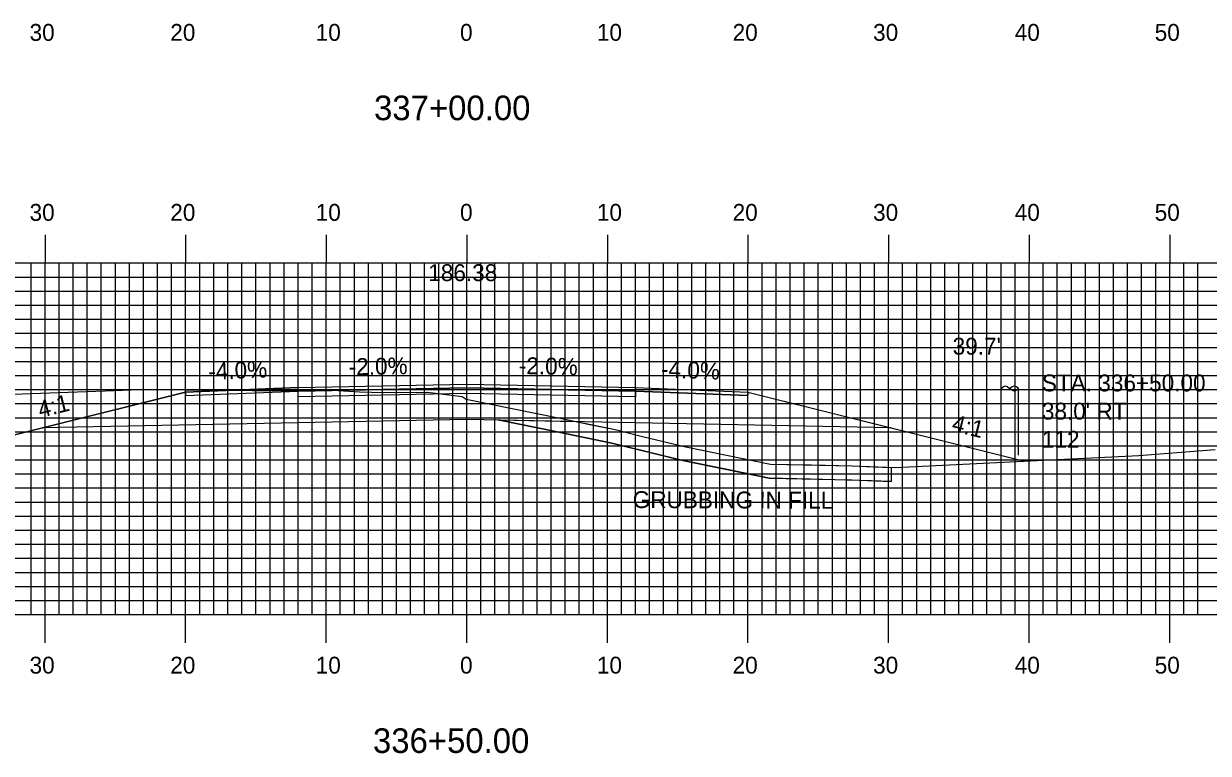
# Model space of a CAD drawing. Extents: x 1823571 to 1823914, y 442310 to 442530.
# Drawn here: x 1823705.4 to 1823789.6, y 442363.2 to 442415.1 of the extents above; entities that cross this region are included whole.
import ezdxf

# ---------------------------------------------------------------- set-up
doc = ezdxf.new("R2010")
doc.units = 0
for name, color, linetype in [('ANNOTATION', 7, 'Continuous'), ('D_Drainage_Text', 7, 'Continuous'), ('D_Roadway_Centerline', 7, 'Continuous'), ('D_Roadway_Centerline_Text', 7, 'Continuous'), ('D_Roadway_Edge_Shoulder', 7, 'Continuous'), ('D_Roadway_Edge_TW', 7, 'Continuous'), ('D_Roadway_Pavement', 7, 'Continuous'), ('D_Roadway_SlopeLines', 7, 'Continuous'), ('D_Roadway_SubGrade', 7, 'Continuous'), ('D_Text_Standard', 7, 'Continuous'), ('D_Utilities_Pole_Joint', 7, 'Continuous'), ('GRUBBING IN FILL', 7, 'Continuous'), ('H_V ANNOTATION', 7, 'Continuous'), ('MAJOR', 7, 'Continuous'), ('MINOR', 7, 'Continuous'), ('S_Roadway_Centerline', 7, 'Continuous')]:
    doc.layers.add(name, color=color, linetype=linetype)

msp = doc.modelspace()

# ---------------------------------------------------------------- linework, layer by layer
at = {"layer": 'D_Roadway_Centerline'}
msp.add_lwpolyline([(1823679.402, 442384.927), (1823702.726, 442385.394), (1823706.726, 442386.394), (1823716.9, 442388.937), (1823724.9, 442389.257), (1823736.9, 442389.497), (1823748.9, 442389.257), (1823756.9, 442388.937), (1823767.074, 442386.394), (1823771.074, 442385.394), (1823776.57, 442384.02)], dxfattribs=at)
at = {"layer": 'D_Roadway_Edge_Shoulder'}
for points in [[(1823724.9, 442389.257), (1823716.9, 442388.937), (1823716.9, 442388.687), (1823724.9, 442389.007)], [(1823748.9, 442389.257), (1823756.9, 442388.937), (1823756.9, 442388.687), (1823748.9, 442389.007)]]:
    msp.add_lwpolyline(points, close=True, dxfattribs=at)
at = {"layer": 'D_Roadway_Edge_TW'}
msp.add_lwpolyline([(1823724.9, 442389.007), (1823724.9, 442389.257), (1823736.9, 442389.497), (1823748.9, 442389.257), (1823748.9, 442389.007), (1823736.9, 442389.247)], close=True, dxfattribs=at)
at = {"layer": 'D_Roadway_Pavement'}
msp.add_lwpolyline([(1823724.9, 442388.59), (1823724.9, 442389.007), (1823736.9, 442389.247), (1823748.9, 442389.007), (1823748.9, 442388.59), (1823736.9, 442388.83)], close=True, dxfattribs=at)
at = {"layer": 'D_Roadway_SlopeLines'}
for points in [[(1823716.9, 442388.937), (1823702.726, 442385.394), (1823679.402, 442384.927)], [(1823756.9, 442388.937), (1823771.074, 442385.394), (1823776.57, 442384.02)]]:
    msp.add_lwpolyline(points, dxfattribs=at)
at = {"layer": 'D_Roadway_SubGrade'}
msp.add_lwpolyline([(1823724.9, 442386.757), (1823706.726, 442386.394), (1823716.9, 442388.937), (1823716.9, 442388.687), (1823724.9, 442389.007), (1823736.9, 442389.247), (1823748.9, 442389.007), (1823756.9, 442388.687), (1823756.9, 442388.937), (1823767.074, 442386.394), (1823748.9, 442386.757), (1823736.9, 442386.997)], close=True, dxfattribs=at)
at = {"layer": 'D_Utilities_Pole_Joint'}
for p, q in [((1823774.9, 442389.195), (1823775.056, 442389.305)), ((1823774.9, 442384.437), (1823774.9, 442389.195)), ((1823775.369, 442389.305), (1823775.525, 442389.195)), ((1823775.681, 442389.305), (1823775.525, 442389.195)), ((1823775.525, 442389.195), (1823775.681, 442389.084)), ((1823776.15, 442389.195), (1823775.994, 442389.305)), ((1823775.994, 442389.084), (1823776.15, 442389.195)), ((1823776.15, 442384.437), (1823776.15, 442389.195))]:
    msp.add_line(p, q, dxfattribs=at)
for centre, start, end in [((1823775.213, 442389.084), 90, 125.26439), ((1823775.213, 442389.084), 54.73561, 90), ((1823775.838, 442389.084), 90, 125.26439), ((1823775.838, 442389.305), 234.73561, 270), ((1823775.838, 442389.084), 54.73561, 90), ((1823775.838, 442389.305), 270, 305.26439)]:
    msp.add_arc(centre, 0.271, start, end, dxfattribs=at)
at = {"layer": 'GRUBBING IN FILL'}
msp.add_line((1823767.074, 442383.583), (1823767.074, 442382.582), dxfattribs=at)
msp.add_line((1823767.074, 442383.583), (1823767.074, 442382.582), dxfattribs=at)
msp.add_lwpolyline([(1823739.136, 442386.952), (1823743.435, 442386.073), (1823747.225, 442385.296), (1823749.15, 442384.817), (1823752.254, 442384.07), (1823758.395, 442382.822), (1823764.285, 442382.683), (1823767.074, 442382.582)], dxfattribs=at)
msp.add_lwpolyline([(1823739.136, 442386.952), (1823743.435, 442386.073), (1823747.225, 442385.296), (1823749.15, 442384.817), (1823752.254, 442384.07), (1823758.395, 442382.822), (1823764.285, 442382.683), (1823767.074, 442382.582)], dxfattribs=at)
msp.add_lwpolyline([(1823739.136, 442386.952), (1823744.664, 442386.842), (1823745.541, 442386.662), (1823747.447, 442386.271), (1823749.388, 442385.788), (1823752.471, 442385.046), (1823755.489, 442384.433), (1823758.507, 442383.819), (1823761.411, 442383.751), (1823764.315, 442383.682), (1823765.837, 442383.627), (1823767.074, 442383.583), (1823767.074, 442382.582), (1823765.68, 442382.632), (1823761.34, 442382.752), (1823758.395, 442382.822), (1823755.324, 442383.446), (1823752.254, 442384.07), (1823750.702, 442384.443), (1823747.225, 442385.296), (1823743.435, 442386.073)], close=True, dxfattribs=at)
msp.add_lwpolyline([(1823739.136, 442386.952), (1823744.664, 442386.842), (1823745.541, 442386.662), (1823747.447, 442386.271), (1823749.388, 442385.788), (1823752.471, 442385.046), (1823755.489, 442384.433), (1823758.507, 442383.819), (1823761.411, 442383.751), (1823764.315, 442383.682), (1823765.837, 442383.627), (1823767.074, 442383.583), (1823767.074, 442382.582), (1823765.68, 442382.632), (1823761.34, 442382.752), (1823758.395, 442382.822), (1823755.324, 442383.446), (1823752.254, 442384.07), (1823750.702, 442384.443), (1823747.225, 442385.296), (1823743.435, 442386.073)], close=True, dxfattribs=at)
at = {"layer": 'MAJOR'}
for p, q in [((1823706.9, 442400.119), (1823706.9, 442398.115)), ((1823716.9, 442400.119), (1823716.9, 442398.115)), ((1823726.9, 442400.119), (1823726.9, 442398.115)), ((1823736.9, 442400.119), (1823736.9, 442398.115)), ((1823746.9, 442400.119), (1823746.9, 442398.115)), ((1823756.9, 442400.119), (1823756.9, 442398.115)), ((1823766.9, 442400.119), (1823766.9, 442398.115)), ((1823776.9, 442400.119), (1823776.9, 442398.115)), ((1823786.9, 442400.119), (1823786.9, 442398.115)), ((1823596.9, 442398.115), (1823876.9, 442398.115)), ((1823596.9, 442398.115), (1823876.9, 442398.115)), ((1823706.9, 442373.115), (1823706.9, 442398.115)), ((1823716.9, 442373.115), (1823716.9, 442398.115)), ((1823726.9, 442373.115), (1823726.9, 442398.115)), ((1823736.9, 442373.115), (1823736.9, 442398.115)), ((1823746.9, 442373.115), (1823746.9, 442398.115)), ((1823756.9, 442373.115), (1823756.9, 442398.115)), ((1823766.9, 442373.115), (1823766.9, 442398.115)), ((1823776.9, 442373.115), (1823776.9, 442398.115)), ((1823786.9, 442373.115), (1823786.9, 442398.115)), ((1823596.9, 442393.115), (1823876.9, 442393.115)), ((1823596.9, 442388.115), (1823876.9, 442388.115)), ((1823596.9, 442383.115), (1823876.9, 442383.115)), ((1823596.9, 442378.115), (1823876.9, 442378.115)), ((1823596.9, 442373.115), (1823876.9, 442373.115)), ((1823706.9, 442371.111), (1823706.9, 442373.115)), ((1823716.9, 442371.111), (1823716.9, 442373.115)), ((1823726.9, 442371.111), (1823726.9, 442373.115)), ((1823736.9, 442371.111), (1823736.9, 442373.115)), ((1823746.9, 442371.111), (1823746.9, 442373.115)), ((1823756.9, 442371.111), (1823756.9, 442373.115)), ((1823766.9, 442371.111), (1823766.9, 442373.115)), ((1823776.9, 442371.111), (1823776.9, 442373.115)), ((1823786.9, 442371.111), (1823786.9, 442373.115))]:
    msp.add_line(p, q, dxfattribs=at)
at = {"layer": 'MINOR'}
for p, q in [((1823705.9, 442373.115), (1823705.9, 442398.115)), ((1823707.9, 442373.115), (1823707.9, 442398.115)), ((1823708.9, 442373.115), (1823708.9, 442398.115)), ((1823709.9, 442373.115), (1823709.9, 442398.115)), ((1823710.9, 442373.115), (1823710.9, 442398.115)), ((1823711.9, 442373.115), (1823711.9, 442398.115)), ((1823712.9, 442373.115), (1823712.9, 442398.115)), ((1823713.9, 442373.115), (1823713.9, 442398.115)), ((1823714.9, 442373.115), (1823714.9, 442398.115)), ((1823715.9, 442373.115), (1823715.9, 442398.115)), ((1823717.9, 442373.115), (1823717.9, 442398.115)), ((1823718.9, 442373.115), (1823718.9, 442398.115)), ((1823719.9, 442373.115), (1823719.9, 442398.115)), ((1823720.9, 442373.115), (1823720.9, 442398.115)), ((1823721.9, 442373.115), (1823721.9, 442398.115)), ((1823722.9, 442373.115), (1823722.9, 442398.115)), ((1823723.9, 442373.115), (1823723.9, 442398.115)), ((1823724.9, 442373.115), (1823724.9, 442398.115)), ((1823725.9, 442373.115), (1823725.9, 442398.115)), ((1823727.9, 442373.115), (1823727.9, 442398.115)), ((1823728.9, 442373.115), (1823728.9, 442398.115)), ((1823729.9, 442373.115), (1823729.9, 442398.115)), ((1823730.9, 442373.115), (1823730.9, 442398.115)), ((1823731.9, 442373.115), (1823731.9, 442398.115)), ((1823732.9, 442373.115), (1823732.9, 442398.115)), ((1823733.9, 442373.115), (1823733.9, 442398.115)), ((1823734.9, 442373.115), (1823734.9, 442398.115)), ((1823735.9, 442373.115), (1823735.9, 442398.115)), ((1823737.9, 442373.115), (1823737.9, 442398.115)), ((1823738.9, 442373.115), (1823738.9, 442398.115)), ((1823739.9, 442373.115), (1823739.9, 442398.115)), ((1823740.9, 442373.115), (1823740.9, 442398.115)), ((1823741.9, 442373.115), (1823741.9, 442398.115)), ((1823742.9, 442373.115), (1823742.9, 442398.115)), ((1823743.9, 442373.115), (1823743.9, 442398.115)), ((1823744.9, 442373.115), (1823744.9, 442398.115)), ((1823745.9, 442373.115), (1823745.9, 442398.115)), ((1823747.9, 442373.115), (1823747.9, 442398.115)), ((1823748.9, 442373.115), (1823748.9, 442398.115)), ((1823749.9, 442373.115), (1823749.9, 442398.115)), ((1823750.9, 442373.115), (1823750.9, 442398.115)), ((1823751.9, 442373.115), (1823751.9, 442398.115)), ((1823752.9, 442373.115), (1823752.9, 442398.115)), ((1823753.9, 442373.115), (1823753.9, 442398.115)), ((1823754.9, 442373.115), (1823754.9, 442398.115)), ((1823755.9, 442373.115), (1823755.9, 442398.115)), ((1823757.9, 442373.115), (1823757.9, 442398.115)), ((1823758.9, 442373.115), (1823758.9, 442398.115)), ((1823759.9, 442373.115), (1823759.9, 442398.115)), ((1823760.9, 442373.115), (1823760.9, 442398.115)), ((1823761.9, 442373.115), (1823761.9, 442398.115)), ((1823762.9, 442373.115), (1823762.9, 442398.115)), ((1823763.9, 442373.115), (1823763.9, 442398.115)), ((1823764.9, 442373.115), (1823764.9, 442398.115)), ((1823765.9, 442373.115), (1823765.9, 442398.115)), ((1823767.9, 442373.115), (1823767.9, 442398.115)), ((1823768.9, 442373.115), (1823768.9, 442398.115)), ((1823769.9, 442373.115), (1823769.9, 442398.115)), ((1823770.9, 442373.115), (1823770.9, 442398.115)), ((1823771.9, 442373.115), (1823771.9, 442398.115)), ((1823772.9, 442373.115), (1823772.9, 442398.115)), ((1823773.9, 442373.115), (1823773.9, 442398.115)), ((1823774.9, 442373.115), (1823774.9, 442398.115)), ((1823775.9, 442373.115), (1823775.9, 442398.115)), ((1823777.9, 442373.115), (1823777.9, 442398.115)), ((1823778.9, 442373.115), (1823778.9, 442398.115)), ((1823779.9, 442373.115), (1823779.9, 442398.115)), ((1823780.9, 442373.115), (1823780.9, 442398.115)), ((1823781.9, 442373.115), (1823781.9, 442398.115)), ((1823782.9, 442373.115), (1823782.9, 442398.115)), ((1823783.9, 442373.115), (1823783.9, 442398.115)), ((1823784.9, 442373.115), (1823784.9, 442398.115)), ((1823785.9, 442373.115), (1823785.9, 442398.115)), ((1823787.9, 442373.115), (1823787.9, 442398.115)), ((1823788.9, 442373.115), (1823788.9, 442398.115)), ((1823596.9, 442397.115), (1823876.9, 442397.115)), ((1823596.9, 442396.115), (1823876.9, 442396.115)), ((1823596.9, 442395.115), (1823876.9, 442395.115)), ((1823596.9, 442394.115), (1823876.9, 442394.115)), ((1823596.9, 442392.115), (1823876.9, 442392.115)), ((1823596.9, 442391.115), (1823876.9, 442391.115)), ((1823596.9, 442390.115), (1823876.9, 442390.115)), ((1823596.9, 442389.115), (1823876.9, 442389.115)), ((1823596.9, 442387.115), (1823876.9, 442387.115)), ((1823596.9, 442386.115), (1823876.9, 442386.115)), ((1823596.9, 442385.115), (1823876.9, 442385.115)), ((1823596.9, 442384.115), (1823876.9, 442384.115)), ((1823596.9, 442382.115), (1823876.9, 442382.115)), ((1823596.9, 442381.115), (1823876.9, 442381.115)), ((1823596.9, 442380.115), (1823876.9, 442380.115)), ((1823596.9, 442379.115), (1823876.9, 442379.115)), ((1823596.9, 442377.115), (1823876.9, 442377.115)), ((1823596.9, 442376.115), (1823876.9, 442376.115)), ((1823596.9, 442375.115), (1823876.9, 442375.115)), ((1823596.9, 442374.115), (1823876.9, 442374.115))]:
    msp.add_line(p, q, dxfattribs=at)
at = {"layer": 'S_Roadway_Centerline'}
msp.add_lwpolyline([(1823701.322, 442388.663), (1823711.186, 442389.029), (1823713.648, 442389.12), (1823716.926, 442389.105), (1823724.01, 442389.027), (1823726.998, 442389.086), (1823729.261, 442388.95), (1823730.975, 442388.899), (1823734.104, 442388.919), (1823734.871, 442388.84), (1823736.578, 442388.618), (1823736.862, 442388.438), (1823743.636, 442387.052), (1823747.447, 442386.271), (1823749.388, 442385.788), (1823752.471, 442385.046), (1823758.507, 442383.819), (1823764.315, 442383.682), (1823767.359, 442383.572), (1823784.702, 442384.415), (1823790.13, 442384.854)], dxfattribs=at)

# ---------------------------------------------------------------- texts
at = {"layer": 'ANNOTATION'}
for s, rotation, p in [('-4.0%', 2.29061, (1823718.532, 442389.804)), ('-2.0%', 1.14576, (1823728.506, 442390.13)), ('-2.0%', 358.85424, (1823740.586, 442390.224)), ('-4.0%', 357.70939, (1823750.692, 442389.987)), ('4:1', 14.03624, (1823706.563, 442387.091)), ('4:1', 345.96376, (1823771.328, 442386.192))]:
    msp.add_text(s, height=1.2, rotation=rotation, dxfattribs=at).set_placement(p)
at = {"layer": 'D_Drainage_Text'}
for s, p in [('STA. 336+50.00', (1823777.804, 442388.983)), ("38.0' RT", (1823777.804, 442386.979)), ('112', (1823777.804, 442384.975))]:
    msp.add_text(s, height=1.2, dxfattribs=at).set_placement(p)
at = {"layer": 'D_Roadway_Centerline'}
for s, p in [('C', (1823736.895, 442389.497)), ('L', (1823736.9, 442389.49))]:
    msp.add_text(s, height=0.0146, dxfattribs=at).set_placement(p)
at = {"layer": 'D_Roadway_Centerline_Text'}
msp.add_text('186.38', height=1.2, dxfattribs=at).set_placement((1823734.155, 442396.826))
at = {"layer": 'D_Text_Standard'}
msp.add_text("39.7'", height=1.2, dxfattribs=at).set_placement((1823771.459, 442391.6))
at = {"layer": 'GRUBBING IN FILL'}
msp.add_text('GRUBBING IN FILL', height=1.2, rotation=359.80532, dxfattribs=at).set_placement((1823748.697, 442380.688))
at = {"layer": 'H_V ANNOTATION'}
for s, height, p in [('30', 1.2, (1823705.797, 442413.915)), ('20', 1.2, (1823715.808, 442413.915)), ('10', 1.2, (1823726.151, 442413.915)), ('0', 1.2, (1823736.418, 442413.915)), ('10', 1.2, (1823746.151, 442413.915)), ('20', 1.2, (1823755.808, 442413.915)), ('30', 1.2, (1823765.797, 442413.915)), ('40', 1.2, (1823775.872, 442413.915)), ('50', 1.2, (1823785.829, 442413.915)), ('337+00.00', 1.75, (1823730.299, 442408.271)), ('30', 1.2, (1823705.797, 442401.115)), ('20', 1.2, (1823715.808, 442401.115)), ('10', 1.2, (1823726.151, 442401.115)), ('0', 1.2, (1823736.418, 442401.115)), ('10', 1.2, (1823746.151, 442401.115)), ('20', 1.2, (1823755.808, 442401.115)), ('30', 1.2, (1823765.797, 442401.115)), ('40', 1.2, (1823775.872, 442401.115)), ('50', 1.2, (1823785.829, 442401.115)), ('30', 1.2, (1823705.797, 442368.915)), ('20', 1.2, (1823715.808, 442368.915)), ('10', 1.2, (1823726.151, 442368.915)), ('0', 1.2, (1823736.418, 442368.915)), ('10', 1.2, (1823746.151, 442368.915)), ('20', 1.2, (1823755.808, 442368.915)), ('30', 1.2, (1823765.797, 442368.915)), ('40', 1.2, (1823775.872, 442368.915)), ('50', 1.2, (1823785.829, 442368.915)), ('336+50.00', 1.75, (1823730.221, 442363.271))]:
    msp.add_text(s, height=height, dxfattribs=at).set_placement(p)
at = {"layer": 'S_Roadway_Centerline'}
for s, p in [('L', (1823713.64, 442389.112)), ('C', (1823713.643, 442389.12))]:
    msp.add_text(s, height=0.0146, dxfattribs=at).set_placement(p)

doc.saveas('drawing.dxf')
